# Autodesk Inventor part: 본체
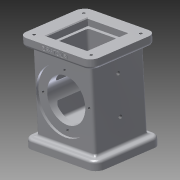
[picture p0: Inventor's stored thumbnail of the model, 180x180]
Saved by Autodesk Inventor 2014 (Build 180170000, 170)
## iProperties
Created: 2017-08
Part Number: 본체
Material: 알루미늄 6061
Document SubType Name: Modeling
Designer: 601-03
Density: 2.71 g/cm^3
Appearance: 알루미늄 - 평지
Mass: 872.386 g
Surface Area: 642.236 cm^2
Volume: 321.914 cm^3
Author: 601-03
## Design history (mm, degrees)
sketch "스케치1"
  geometry: L1 (-46, -41)-(46, -41); L2 (46, -41)-(46, 41); L3 (46, 41)-(-46, 41); L4 (-46, 41)-(-46, -41); L5 (-46, -41)-(46, 41); L6 (46, -41)-(-46, 41); 1 further point
  constraints: 12 end point, 2 midpoint, 2 parallel, 1 horizontal, 1 perpendicular
  dimensions: "d0" = 92 distance between parallel lines of L4 L2; "d1" = 82 distance between parallel lines of L1 L3
extrude "돌출1" new body sketch "스케치1" distance "d2" = 10; taper "d3" = 0 deg
sketch "스케치2"
  geometry: L1 (-37, -33)-(37, -33); L2 (37, -33)-(37, 33); L3 (37, 33)-(-37, 33); L4 (-37, 33)-(-37, -33); L5 (-37, -33)-(37, 33); L6 (37, -33)-(-37, 33); 1 further point
  constraints: 12 end point, 2 midpoint, 2 parallel, 1 horizontal, 1 perpendicular
  dimensions: "d4" = 74 distance between parallel lines of L4 L2; "d5" = 66 distance between parallel lines of L1 L3
extrude "돌출2" join sketch "스케치2" distance "d6" = 88; taper "d7" = 0 deg
sketch "스케치3"
  geometry: L1 (46, 41)-(-46, 41) reference; L2 (-46, 41)-(-46, -41) reference; L3 (46, -41)-(-46, -41); L4 (-46, -41)-(-46, 41); L5 (-46, 41)-(46, 41); L6 (46, 41)-(46, -41); L7 (46, -41)-(-46, 41); L8 (-46, -41)-(46, 41); 1 further point
  constraints: 12 end point, 2 midpoint, 2 parallel, 1 horizontal, 1 perpendicular
extrude "돌출3" join sketch "스케치3" distance "d8" = 10; taper "d9" = 0 deg
sketch "스케치7"
  geometry: L1 (0, 0)-(0, -88) reference; L2 (74, 0)-(74, -88) reference; L3 (74, -44)-(0, -44); C1 r 35 at (37, -44); 1 further point
  constraints: 3 midpoint, 2 end point, 1 centre point
  dimensions: "d12" = 70 diameter of C1
extrude "돌출4" cut sketch "스케치7" distance "d13" = 3; taper "d14" = 0 deg
sketch "스케치8"
  geometry: C1 r 35 at (0, 0) reference; C2 r 24 at (0, 0); 1 further point
  constraints: 1 centre point, 1 coincident
  dimensions: "d15" = 48 diameter of C2
extrude "돌출5" cut sketch "스케치8" distance "d16" = 100; taper "d17" = 0 deg
sketch "스케치9"
  geometry: L1 (-26, -26)-(26, -26); L2 (26, -26)-(26, 26); L3 (26, 26)-(-26, 26); L4 (-26, 26)-(-26, -26); L5 (-26, -26)-(26, 26); L6 (26, -26)-(-26, 26); 1 further point
  constraints: 12 end point, 2 midpoint, 2 parallel, 1 horizontal, 1 perpendicular
  dimensions: "d18" = 52 distance between parallel lines of L2 L4; "d19" = 52 distance between parallel lines of L1 L3
extrude "돌출6" cut sketch "스케치9" distance "d20" = 8; taper "d21" = 0 deg
sketch "스케치10"
  geometry: L1 (-22, -22)-(22, -22); L2 (22, -22)-(22, 22); L3 (22, 22)-(-22, 22); L4 (-22, 22)-(-22, -22); L5 (-22, -22)-(22, 22); L6 (22, -22)-(-22, 22); 1 further point
  constraints: 12 end point, 2 midpoint, 2 parallel, 1 horizontal, 1 perpendicular
  dimensions: "d22" = 44 distance between parallel lines of L4 L2; "d23" = 44 distance between parallel lines of L1 L3
extrude "돌출7" cut sketch "스케치10" distance "d24" = 74; taper "d25" = 0 deg
sketch "스케치11"
  geometry: L1 (-24, -24)-(24, -24); L2 (24, -24)-(24, 24); L3 (24, 24)-(-24, 24); L4 (-24, 24)-(-24, -24); L5 (-24, -24)-(24, 24); L6 (24, -24)-(-24, 24); 1 further point
  constraints: 12 end point, 2 midpoint, 2 parallel, 1 horizontal, 1 perpendicular
  dimensions: "d26" = 48 distance between parallel lines of L1 L3; "d27" = 48 distance between parallel lines of L4 L2
extrude "돌출8" cut sketch "스케치11" distance "d28" = 16; taper "d29" = 0 deg
sketch "스케치12"
  geometry: L1 (-36, -31)-(36, -31); L2 (36, -31)-(36, 31); L3 (36, 31)-(-36, 31); L4 (-36, 31)-(-36, -31); L5 (-36, -31)-(36, 31); L6 (36, -31)-(-36, 31); 5 further points
  constraints: 12 end point, 4 coincident, 2 midpoint, 2 parallel, 1 horizontal, 1 perpendicular
  dimensions: "d30" = 72 distance between parallel lines of L2 L4; "d31" = 62 distance between parallel lines of L1 L3
hole "구멍1" sketch "스케치12" at (-36, 31), (-36, -31), (36, -31), (36, 31) diameter "d32" = 3.242; stored, may be unused: countersink angle "d36" = 90 deg, drill point angle "d38" = 118 deg; dims "d33" = 4, "d34" = 4, "d35" = 2, "d37" = 6
sketch "스케치13"
  geometry: L1 (-36, -31)-(36, -31); L2 (36, -31)-(36, 31); L3 (36, 31)-(-36, 31); L4 (-36, 31)-(-36, -31); L5 (-36, -31)-(36, 31); L6 (36, -31)-(-36, 31); 5 further points
  constraints: 12 end point, 4 coincident, 2 midpoint, 2 parallel, 1 horizontal, 1 perpendicular
  dimensions: "d39" = 72 distance between parallel lines of L2 L4; "d40" = 62 distance between parallel lines of L1 L3
hole "구멍2" sketch "스케치13" at (-36, 31), (-36, -31), (36, -31), (36, 31) diameter "d41" = 3.242; stored, may be unused: countersink angle "d45" = 90 deg, drill point angle "d47" = 118 deg; dims "d42" = 4, "d43" = 4, "d44" = 2, "d46" = 6
sketch "스케치14" dims "d48" = 58
  geometry: C1 r 35 at (0, 0) reference; 3 further points
  constraints: 1 coincident, 1 horizontal alignment, 2 other
hole "구멍3" sketch "스케치14" at (29, 0) diameter "d49" = 3.242; stored, may be unused: countersink angle "d53" = 90 deg, drill point angle "d55" = 118 deg; dims "d50" = 4, "d51" = 4, "d52" = 2, "d54" = 6
sketch "스케치15" dims "d59" = 58
  geometry: C1 r 35 at (0, 0) reference; 3 further points
  constraints: 1 coincident, 1 horizontal alignment, 2 other
hole "구멍4" sketch "스케치15" at (29, 0) diameter "d60" = 3.242; stored, may be unused: countersink angle "d64" = 90 deg, drill point angle "d66" = 118 deg; dims "d61" = 4, "d62" = 4, "d63" = 2, "d65" = 6
fillet "모깎기1" dims "d70" = 10
fillet "모깎기2" dims "d71" = 10
sketch "스케치16"
  geometry: L1 (10, 2)-(10, 64) reference; L2 (10, 33)-(-28, 33); L3 (-28, 33)-(-70, 33); 1 further point
  constraints: 4 end point, 2 coincident, 1 collinear, 1 perpendicular
  dimensions: "d72" = 38 distance of L2.end L2.start; "d73" = 42 distance of L3.start L3.end
hole "구멍5" sketch "스케치16" at (-28, 33), (-70, 33) diameter "d74" = 4.134; stored, may be unused: countersink angle "d78" = 90 deg, drill point angle "d80" = 118 deg; dims "d75" = 22, "d76" = 4, "d77" = 2, "d79" = 22
fillet "모깎기3" dims "d81" = 3
fillet "모깎기5" dims "d83" = 3
fillet "모깎기6" dims "d84" = 3
fillet "모깎기7" dims "d85" = 3
chamfer "모따기1" distance "d86" = 1; stored, may be unused: second distance "d87" = 2, angle "d88" = 45 deg
fillet "모깎기8" dims "d89" = 3
fillet "모깎기9" dims "d90" = 3
fillet "모깎기10" dims "d91" = 3
fillet "모깎기11" dims "d92" = 3
sketch "스케치17"
  geometry: L1 (0, 108)-(72, 108) reference; L2 (-10, 108)-(-10, 101) reference; 2 further points
  constraints: 1 other
  dimensions: "d93" = 4 distance from line of L1 point (36, 104); "d94" = 46 distance from line of L2 point (36, 104)
feature "엠보싱1" sketch "스케치17" dims "d0" = 92, "d1" = 82, "d95" = 0.5, "d96" = 0
node "솔리드1"
mirror "대칭1"
pattern_circular "원형 패턴1" dims angle "d57" = 360 deg
pattern_circular "원형 패턴2" dims angle "d68" = 360 deg
